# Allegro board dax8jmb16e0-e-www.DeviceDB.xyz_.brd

Outline 242.5 x 137.69 mm; copper layers: TOP, SVCC, IN1, IN2, SGND, BOTTOM. Coordinates in mm from the lower left corner of the outline.

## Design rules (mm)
net group W10(10)-T12B: nets HPOUT_L HPOUT_R
net group DFP-S4(4.5)W3.8(4.5)-T12B: nets C_TX0_HDMI+ C_TX0_HDMI- C_TX1_HDMI+ C_TX1_HDMI- C_TX2_HDMI+ C_TX2_HDMI- C_TXC_HDMI+ C_TXC_HDMI- CK_XDP_N CK_XDP_P CK_XDP_P_R CLK_PCIE_LANN CLK_PCIE_LANP CLK_PCIE_SSDN CLK_PCIE_SSDP CLK_PCIE_WLANN CLK_PCIE_WLANP CLK_PCIE_WWANN CLK_PCIE_WWANP DDI2_AUX_DN DDI2_AUX_DN_C DDI2_AUX_DP DDI2_AUX_DP_C DDI2_TX0_DN DDI2_TX0_DN_C DDI2_TX0_DP DDI2_TX0_DP_C DDI2_TX1_DN DDI2_TX1_DN_C DDI2_TX1_DP DDI2_TX1_DP_C DDI2_TX2_DN DDI2_TX2_DN_C DDI2_TX2_DP DDI2_TX2_DP_C DDI2_TX3_DN DDI2_TX3_DN_C DDI2_TX3_DP DDI2_TX3_DP_C EDIDCLK_R EDIDDATA_R IN_CLK IN_CLK# IN_D0 IN_D0# IN_D1 IN_D1# IN_D2 IN_D2# INT_EDP_AUXN INT_EDP_AUXP INT_EDP_TXN0 INT_EDP_TXN1 INT_EDP_TXP0 INT_EDP_TXP1 M_A_CLKN0 M_A_CLKN1 M_A_CLKP0 M_A_CLKP1 M_A_DQSN0 M_A_DQSN1 M_A_DQSN2 M_A_DQSN3 M_A_DQSN4 M_A_DQSN5 M_A_DQSN6 M_A_DQSN7 M_A_DQSP0 M_A_DQSP1 M_A_DQSP2 M_A_DQSP3 M_A_DQSP4 M_A_DQSP5 M_A_DQSP6 M_A_DQSP7 M_B_CLKN0 M_B_CLKN1 M_B_CLKP0 M_B_CLKP1 M_B_DQSN0 M_B_DQSN1 M_B_DQSN2 M_B_DQSN3 M_B_DQSN4 M_B_DQSN5 M_B_DQSN6 M_B_DQSN7 M_B_DQSP0 M_B_DQSP1 M_B_DQSP2 M_B_DQSP3 M_B_DQSP4 M_B_DQSP5 M_B_DQSP6 M_B_DQSP7 MDI0+ MDI0+_1 MDI0- MDI0-_1 MDI1+ MDI1+_1 MDI1- MDI1-_1 MDI2+ MDI2+_1 MDI2- MDI2-_1 MDI3+ MDI3+_1 MDI3- MDI3-_1 MUX_SBU1 MUX_SBU2 PCIE_RXN5_LAN PCIE_RXN5_LAN_L PCIE_RXN6_WLAN PCIE_RXN8_SSD PCIE_RXN9_SSD PCIE_RXN10_SSD PCIE_RXN10_WWAN PCIE_RXN11_SSD PCIE_RXN11_SSD_C PCIE_RXN12_SSD PCIE_RXN12_SSD_C PCIE_RXP5_LAN PCIE_RXP5_LAN_L PCIE_RXP6_WLAN PCIE_RXP8_SSD PCIE_RXP9_SSD PCIE_RXP10_SSD PCIE_RXP10_WWAN PCIE_RXP11_SSD PCIE_RXP11_SSD_C PCIE_RXP12_SSD PCIE_RXP12_SSD_C PCIE_TXN5_LAN PCIE_TXN5_LAN_C PCIE_TXN6_WLAN PCIE_TXN6_WLAN_C PCIE_TXN8_SSD PCIE_TXN9_SSD PCIE_TXN9_SSD_C PCIE_TXN10_SSD PCIE_TXN10_SSD_C1 PCIE_TXN10_WWAN PCIE_TXN10_WWAN_C PCIE_TXN11_SSD PCIE_TXN11_SSD_C PCIE_TXN12_SSD PCIE_TXN12_SSD_C PCIE_TXP5_LAN PCIE_TXP5_LAN_C PCIE_TXP6_WLAN PCIE_TXP6_WLAN_C PCIE_TXP8_SSD PCIE_TXP9_SSD PCIE_TXP9_SSD_C PCIE_TXP10_SSD PCIE_TXP10_SSD_C1 PCIE_TXP10_WWAN PCIE_TXP10_WWAN_C PCIE_TXP11_SSD PCIE_TXP11_SSD_C PCIE_TXP12_SSD PCIE_TXP12_SSD_C SATA_RXN7 SATA_RXN7_C SATA_RXP7 SATA_RXP7_C SATA_TXN7 SATA_TXN7_C SATA_TXP7 SATA_TXP7_C TX0_HDMI+ TX0_HDMI- TX1_HDMI+ TX1_HDMI- TX2_HDMI+ TX2_HDMI- TXC_HDMI+ TXC_HDMI- TXLOUT0+ TXLOUT0- TXLOUT1+ TXLOUT1- TYPEC_SBU1 TYPEC_SBU2 USB30_RX1+ USB30_RX1- USB30_RX3+ USB30_RX3- USB30_RX4+ USB30_RX4+_C USB30_RX4- USB30_RX4-_C USB30_TX1+ USB30_TX1+_C USB30_TX1- USB30_TX1-_C USB30_TX3+ USB30_TX3+_C USB30_TX3- USB30_TX3-_C USB30_TX4+ USB30_TX4+_C USB30_TX4- USB30_TX4-_C USB_CYPRESS_BOT_DN USB_CYPRESS_BOT_DP USB_CYPRESS_BOT_L_DN USB_CYPRESS_BOT_L_DP USB_CYPRESS_TOP_DN USB_CYPRESS_TOP_DP USB_CYPRESS_TOP_L_DN USB_CYPRESS_TOP_L_DP USBP1+ USBP1+_C USBP1- USBP1-_C USBP2+ USBP2- USBP3+_TS USBP3+_TS_C USBP3-_TS USBP3-_TS_C USBP4+_C USBP4-_C USBP5+ USBP5+_C USBP5- USBP5-_C USBP6+_C USBP6-_C USBP7+ USBP7- USBP10+_WWAN USBP10+_WWAN_C USBP10-_WWAN USBP10-_WWAN_C WR_CLK_DN WR_CLK_DP WR_LANE0_DN WR_LANE0_DP WR_LANE1_DN WR_LANE1_DP WT_CLK_DN WT_CLK_DP WT_LANE0_DN WT_LANE0_DP WT_LANE1_DN WT_LANE1_DP
net group DFP-S4.5(6)W3.8(4.5)-T12B: nets CK_XDP_N_R
net group DFP-S4.5(6)W4(5)-T12B: nets DPB_DDCCLK DPB_DDCDATA HDMI_UP_CLK HDMI_UP_DATA
net group DFP-S12(8)W3.8(4.5)-T12B: nets TYPEC3_RX1N TYPEC3_RX1N_C TYPEC3_RX1P TYPEC3_RX1P_C TYPEC3_RX2N TYPEC3_RX2N_C TYPEC3_RX2P TYPEC3_RX2P_C TYPEC3_TX1N TYPEC3_TX1N_C TYPEC3_TX1P TYPEC3_TX1P_C TYPEC3_TX2N TYPEC3_TX2N_C TYPEC3_TX2P TYPEC3_TX2P_C
net group W4(5)-T1B: nets H_CPU_SVIDALRT# PM_THRMTRIP# RTC_X1 RTC_X2 XTAL1 XTAL2 XTAL24_IN XTAL24_OUT
net group W4(5)-T12B: nets ACZ_BCLK ACZ_RST# ACZ_RST#_AUDIO ACZ_SDIN0 ACZ_SDOUT ACZ_SDOUT_AUDIO ACZ_SYNC ACZ_SYNC_AUDIO BIT_CLK_AUDIO CCG5_I2C_SCL_MUX CCG5_I2C_SDA_MUX CLK_PCI_EC_R CPU_PROCHOT# CPU_PROCHOT#_R DDR3_DRAMRST# DIGITAL_CLK DIGITAL_CLK_L DIGITAL_D1 EC_PECI EC_PECI_R FAN1_PWM H_VCCST_PWRGD HD_SDIN0 IM_5S_CLK IM_5S_DAT LAD0 LAD0_L LAD1 LAD1_L LAD2 LAD2_L LAD3 LAD3_L LFRAME# LPC_ESPI_CLK M_A_DQ0 M_A_DQ1 M_A_DQ2 M_A_DQ3 M_A_DQ4 M_A_DQ5 M_A_DQ6 M_A_DQ7 M_A_DQ8 M_A_DQ9 M_A_DQ10 M_A_DQ11 M_A_DQ12 M_A_DQ13 M_A_DQ14 M_A_DQ15 M_A_DQ16 M_A_DQ17 M_A_DQ18 M_A_DQ19 M_A_DQ20 M_A_DQ21 M_A_DQ22 M_A_DQ23 M_A_DQ24 M_A_DQ25 M_A_DQ26 M_A_DQ27 M_A_DQ28 M_A_DQ29 M_A_DQ30 M_A_DQ31 M_A_DQ32 M_A_DQ33 M_A_DQ34 M_A_DQ35 M_A_DQ36 M_A_DQ37 M_A_DQ38 M_A_DQ39 M_A_DQ40 M_A_DQ41 M_A_DQ42 M_A_DQ43 M_A_DQ44 M_A_DQ45 M_A_DQ46 M_A_DQ47 M_A_DQ48 M_A_DQ49 M_A_DQ50 M_A_DQ51 M_A_DQ52 M_A_DQ53 M_A_DQ54 M_A_DQ55 M_A_DQ56 M_A_DQ57 M_A_DQ58 M_A_DQ59 M_A_DQ60 M_A_DQ61 M_A_DQ62 M_A_DQ63 M_B_DQ0 M_B_DQ1 M_B_DQ2 M_B_DQ3 M_B_DQ4 M_B_DQ5 M_B_DQ6 M_B_DQ7 M_B_DQ8 M_B_DQ9 M_B_DQ10 M_B_DQ11 M_B_DQ12 M_B_DQ13 M_B_DQ14 M_B_DQ15 M_B_DQ16 M_B_DQ17 M_B_DQ18 M_B_DQ19 M_B_DQ20 M_B_DQ21 M_B_DQ22 M_B_DQ23 M_B_DQ24 M_B_DQ25 M_B_DQ26 M_B_DQ27 M_B_DQ28 M_B_DQ29 M_B_DQ30 M_B_DQ31 M_B_DQ32 M_B_DQ33 M_B_DQ34 M_B_DQ35 M_B_DQ36 M_B_DQ37 M_B_DQ38 M_B_DQ39 M_B_DQ40 M_B_DQ41 M_B_DQ42 M_B_DQ43 M_B_DQ44 M_B_DQ45 M_B_DQ46 M_B_DQ47 M_B_DQ48 M_B_DQ49 M_B_DQ50 M_B_DQ51 M_B_DQ52 M_B_DQ53 M_B_DQ54 M_B_DQ55 M_B_DQ56 M_B_DQ57 M_B_DQ58 M_B_DQ59 M_B_DQ60 M_B_DQ61 M_B_DQ62 M_B_DQ63 MUX_I2C_SCL MUX_I2C_SDA OUT_DPST_PWM PCH_DPST_PWM PCH_KBC_CLK PCH_KBC_DATA PCH_SMB_CLK PCH_SMB_DATA PCH_SMBCLK PCH_SMBDATA PCH_SPI1_CLK PCH_SPI1_CLK_E1 PCH_SPI1_CLK_E2 PCH_SPI1_CLK_R1 PCH_SPI1_CLK_R2 PCH_SPI1_SI PCH_SPI1_SI_E1 PCH_SPI1_SI_E2 PCH_SPI1_SI_R1 PCH_SPI1_SI_R2 PCH_SPI1_SO PCH_SPI1_SO_E1 PCH_SPI1_SO_E2 PCH_SPI1_SO_R1 PCH_SPI1_SO_R2 PCH_SPI_CS0# PCH_SPI_CS0#_R2 PCH_SPI_IO2 PCH_SPI_IO2_R1 PCH_SPI_IO2_R2 PCH_SPI_IO3 PCH_SPI_IO3_R1 PCH_SPI_IO3_R2 PCIE_CLKREQ5# PCIE_CLKREQ_LAN# PCIE_CLKREQ_SSD# PCIE_CLKREQ_WLAN# PD_I2C_SCL3 PD_I2C_SDA3 PLTRST# RSMRST# RTC_RST# S_SD_CLK S_SD_CLK_C S_SD_CMD S_SD_DATA0 S_SD_DATA1 S_SD_DATA2 S_SD_DATA3 SCL_BAT_CHG SD_CD#_BH SD_CD#_PCH SD_CLK SD_CLK_R SD_CMD SD_CMD_C SD_DATA0 SD_DATA0_C SD_DATA1 SD_DATA1_C SD_DATA2 SD_DATA2_C SD_DATA3 SD_DATA3_C SD_WP_BH SD_WP_PCH SDA_BAT_CHG SMB_ME0_CLK SMB_ME0_DAT SMB_PCH_CLK SMB_PCH_DAT SP_CLK SP_DATA SRTC_RST# SUSCLK32_KBC THERM_SCL THERM_SDA TPCLK-1 TPDATA-1 UIM_CLK UIM_DATA VADJ1 VCCSA_VCCSENSE VCCSA_VSSSENSE VCCSENSE VGT_VCCSENSE VGT_VSSSENSE VR_SVID_ALERT# VR_SVID_CLK VR_SVID_DATA VSSSENSE XCLK_BIASREF
net group W5(6.5)-T12B: nets M_A_A0 M_A_A1 M_A_A2 M_A_A3 M_A_A4 M_A_A5 M_A_A6 M_A_A7 M_A_A8 M_A_A9 M_A_A10 M_A_A11 M_A_A12 M_A_A13 M_A_ACT# M_A_ALERT# M_A_BG#0 M_A_BG#1 M_A_BS#0 M_A_BS#1 M_A_CAS# M_A_CKE0 M_A_CKE1 M_A_CS#0 M_A_CS#1 M_A_ODT0 M_A_ODT1 M_A_PARITY M_A_RAS# M_A_WE# M_B_A0 M_B_A1 M_B_A2 M_B_A3 M_B_A4 M_B_A5 M_B_A6 M_B_A7 M_B_A8 M_B_A9 M_B_A10 M_B_A11 M_B_A12 M_B_A13 M_B_ACT# M_B_ALERT# M_B_BG#0 M_B_BG#1 M_B_BS#0 M_B_BS#1 M_B_CAS# M_B_CKE0 M_B_CKE1 M_B_CS#0 M_B_CS#1 M_B_ODT0 M_B_ODT1 M_B_PARITY M_B_RAS# M_B_WE#
net group W5-T12B: nets TYPEC_VBUS
net group W8-T12B: nets DDR_VTT
net group W10-T12B: nets +1.0V_STG +SMDDR_VREF_DQ0 +SMDDR_VREF_DQ1 +VCCSFR +VCCST +VCCSTG CSP_C DDR_VTTREF
net group W12-T12B: nets PCIE_RCOMPN PCIE_RCOMPP SM_RCOMP_0 SM_RCOMP_1 SM_RCOMP_2
net group W15-T12B: nets CFG_RCOMP TYPEC_CC1 TYPEC_CC2
net group W20-T1B: nets EDP_RCOMP
net group W20-T12B: nets +3V_RTC +3V_WLAN_P +3VLCD_CON +5V_HDMIC +SMDDR_VREF_DIMM SM_VREF SMDDR_VREF_DQ0_M3 SMDDR_VREF_DQ1_M1 SMDDR_VREF_DQ1_M3
net group W30-T12B: nets L_SPK+ L_SPK+_R L_SPK- L_SPK-_R R_SPK+ R_SPK+_R R_SPK- R_SPK-_R
net group W40-T12B: nets +1.2V_VCCPLL_OC

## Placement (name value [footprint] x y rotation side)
C400  47P/50V_4  [C0402]  98.71 109.68 270 bottom
C401  *15P/50V_4  [C0402]  149.41 72.27 270 bottom
C402  *15P/50V_4  [C0402]  129.4 71.4 90 top
C403  0.1U/10V/X7R_4  [C0402]  128.84 59.42 180 top
C404  0.1U/16V_4  [C0402]  139.12 69.37 90 top
C405  0.1U/16V_4  [C0402]  152.85 99.39 0 top
C407  0.1U/16V_4  [C0402]  198.66 77.53 270 top
C409  0.1U/16V_4  [C0402]  199.63 77.53 270 top
C416  0.1U/16V_4  [C0402]  193.02 75.37 90 top
C417  0.1U/16V_4  [C0402]  194.04 75.37 90 top
C418  0.1U/16V_4  [C0402]  168.46 92.77 90 bottom
C419  0.1U/16V_4  [C0402]  167.5 92.77 90 bottom
C420  22P/50V_4  [C0402]  128.84 72.24 270 bottom
C421  15P/50V_4  [C0402]  155.61 83.37 0 top
C422  15P/50V_4  [C0402]  153.58 83.37 180 top
C423  *4.7p/50V_4  [C0402]  152.13 98.86 180 bottom
C424  10P/50V_4  [C0402]  145.67 101.65 180 bottom
C425  10P/50V_4  [C0402]  145.68 100.16 180 bottom
C426  1U/6.3V_4  [C0402]  134.07 72.22 90 bottom
C427  0.1U/16V_4  [C0402]  133.1 72.22 90 bottom
C428  1U/6.3V_4  [C0402]  61.5 59.92 0 top
C429  *1U/6.3V_4  [C0402]  61.5 60.89 0 top
C430  1U/6.3V_4  [C0402]  131.66 71.86 180 bottom
C431  0.1U/16V_4  [C0402]  132.93 89.01 90 top
C432  1U/6.3V_4  [C0402]  133.05 92.89 90 top
C433  1U/6.3V_4  [C0402]  131.94 89.01 90 top
C434  *1U/6.3V_4  [C0402]  130.81 91.45 180 top
C435  *0.1U/16V_4  [C0402]  130.95 89.03 90 top
C436  0.1U/16V_4  [C0402]  151.52 103.69 270 bottom
C437  1U/6.3V_4  [C0402]  152 105.09 180 bottom
C438  1U/6.3V_4  [C0402]  132 87 270 top
C439  0.1U/16V_4  [C0402]  125.99 89.11 90 top
C440  0.1U/16V_4  [C0402]  131.73 92.89 90 top
C441  1U/6.3V_4  [C0402]  152.54 103.69 90 bottom
C442  0.1U/16V_4  [C0402]  130.81 90.45 180 top
C443  *1U/6.3V_4  [C0402]  152 107.12 180 bottom
C444  1U/6.3V_4  [C0402]  152 106.1 180 bottom
C445  *0.1U/16V_4  [C0402]  154.54 103.69 270 bottom
C446  0.1U/16V_4  [C0402]  129.2 92.74 90 top
C447  0.1U/16V_4  [C0402]  131.04 87 270 top
C448  1U/6.3V_4  [C0402]  129.83 86.97 270 top
C449  0.1U/16V_4  [C0402]  142.38 86.87 0 bottom
C450  1U/6.3V_4  [C0402]  127.97 89.01 90 top
C451  10U/6.3V_4  [C0402]  156.45 104.32 180 bottom
C452  0.1U/16V_4  [C0402]  129.82 94.55 90 top
C453  *0.1U/16V_4  [C0402]  129.17 90.76 270 top
C454  1U/6.3V_4  [C0402]  153.53 103.69 270 bottom
C455  0.1U/16V_4  [C0402]  131.17 95.04 90 top
C456  1U/6.3V_4  [C0402]  127.92 92.8 90 top
C457  0.1U/16V_4  [C0402]  132.42 90.78 270 top
C458  1U/6.3V_4  [C0402]  127.16 86.54 180 top
C459  1U/6.3V_4  [C0402]  132.42 94.9 90 top
C460  0.1U/16V_4  [C0402]  128.47 94.54 90 top
C461  1U/6.3V_4  [C0402]  127.23 94.54 90 top
C462  0.1U/16V_4  [C0402]  152.74 92.49 270 top
C463  1U/6.3V_4  [C0402]  129.93 89.01 90 top
C464  1U/6.3V_4  [C0402]  130.49 92.82 90 top
C465  1U/6.3V_4  [C0402]  128.94 89.01 90 top
C466  1U/6.3V_4  [C0402]  127.92 91.06 270 top
C467  *0.1U/16V_4  [C0402]  142.37 84.88 0 bottom
C468  0.1U/16V_4  [C0402]  148.83 117.12 180 bottom
C469  1U/6.3V_4  [C0402]  148.83 116.13 180 bottom
C470  1U/6.3V_4  [C0402]  126.96 89.11 90 top
C471  0.1U/16V_4  [C0402]  130.01 72.27 90 bottom
C472  1U/6.3V_4  [C0402]  142.32 99.32 0 bottom
C473  22U/6.3V_6  [C0603]  145.15 97.93 180 bottom
C474  1U/6.3V_4  [C0402]  128.64 108.55 180 bottom
C475  *0.1U/16V_4  [C0402]  128.18 109.35 180 top
C476  22U/6.3V_6  [C0603]  128.77 110.06 180 bottom
C477  *3P/50V_4  [C0402]  128.18 108.39 180 top
C478  *3P/50V_4  [C0402]  128.18 106.05 0 top
C481  10U/6.3V_4  [C0402]  116.87 96.88 180 top
C482  10U/6.3V_4  [C0402]  120.51 91.52 0 top
C483  10U/6.3V_4  [C0402]  115.12 88.12 180 top
C485  10U/6.3V_4  [C0402]  114.16 96.91 180 top
C486  10U/6.3V_4  [C0402]  120.51 93.05 180 top
C490  10U/6.3V_4  [C0402]  120.61 96.88 0 top
C491  10U/6.3V_4  [C0402]  111.03 94.57 90 top
C492  10U/6.3V_4  [C0402]  112.99 94.57 90 top
C493  10U/6.3V_4  [C0402]  120.81 86.04 0 top
C494  10U/6.3V_4  [C0402]  120.48 88.4 180 top
C495  10U/6.3V_4  [C0402]  120.79 94.39 180 top
C496  10U/6.3V_4  [C0402]  120.51 90 180 top
C497  10U/6.3V_4  [C0402]  120.79 95.36 180 top
C508  10U/6.3V_4  [C0402]  113.75 85.91 180 top
C509  10U/6.3V_4  [C0402]  115.48 85.96 0 top
C510  10U/6.3V_4  [C0402]  119.06 86.04 0 top
C518  10U/6.3V_4  [C0402]  115.5 86.92 0 top
C519  10U/6.3V_4  [C0402]  117.33 87.03 180 top
C520  10U/6.3V_4  [C0402]  117.84 93.4 180 top
C521  10U/6.3V_4  [C0402]  120.81 87 0 top
C522  10U/6.3V_4  [C0402]  117.33 86.06 180 top
C523  10U/6.3V_4  [C0402]  117.86 88.6 180 top
C524  10U/6.3V_4  [C0402]  117.97 95.92 180 top
C525  22U/6.3V_6  [C0603]  117.84 89.97 0 top
C526  22U/6.3V_6  [C0603]  123.5 112.93 270 top
C527  22U/6.3V_6  [C0603]  112.89 113.72 270 top
C528  22U/6.3V_6  [C0603]  114.79 95.69 180 top
C529  22U/6.3V_6  [C0603]  119.39 112.91 270 top
C530  22U/6.3V_6  [C0603]  115.17 89.97 180 top
C531  22U/6.3V_6  [C0603]  114.79 94.16 180 top
C532  22U/6.3V_6  [C0603]  113.52 106.1 0 top
C533  22U/6.3V_6  [C0603]  121.42 112.91 270 top
C534  22U/6.3V_6  [C0603]  114.79 92.13 180 top
C535  22U/6.3V_6  [C0603]  109.23 112.91 270 top
C536  22U/6.3V_6  [C0603]  117.46 92.13 0 top
C537  22U/6.3V_6  [C0603]  117.97 94.67 0 top
C538  10U/6.3V_4  [C0402]  112 94.57 90 top
C539  10U/6.3V_4  [C0402]  112.89 107.5 180 top
C540  10U/6.3V_4  [C0402]  118.58 109.28 0 bottom
C541  10U/6.3V_4  [C0402]  116.57 109.28 180 bottom
C546  *0.1U/16V_4  [C0402]  105.72 111.13 0 bottom
C547  22U/6.3V_6  [C0603]  107.22 87.05 90 top
C548  22U/6.3V_6  [C0603]  102.85 87.05 90 top
C549  22U/6.3V_6  [C0603]  101.41 87.05 270 top
C550  22U/6.3V_6  [C0603]  101.84 92.26 0 top
C551  22U/6.3V_6  [C0603]  83.52 90 90 bottom
C552  22U/6.3V_6  [C0603]  104.88 92.26 0 top
C553  22U/6.3V_6  [C0603]  105.77 87.05 90 top
C554  22U/6.3V_6  [C0603]  104.88 94.42 180 top
C555  22U/6.3V_6  [C0603]  108.64 87.05 90 top
C556  22U/6.3V_6  [C0603]  85.05 90 90 bottom
C557  22U/6.3V_6  [C0603]  99.93 87.05 270 top
C558  22U/6.3V_6  [C0603]  87.51 90.02 90 bottom
C559  10U/6.3V_4  [C0402]  104.88 90.53 180 top
C560  10U/6.3V_4  [C0402]  86.14 94.93 90 top
C561  10U/6.3V_4  [C0402]  101.84 90.61 180 top
C562  10U/6.3V_4  [C0402]  87.13 94.93 90 top
C563  22U/6.3V_6  [C0603]  89.04 90.02 90 bottom
C564  22U/6.3V_6  [C0603]  104.33 87.05 270 top
C565  10U/6.3V_4  [C0402]  89.11 92.74 90 top
C566  10U/6.3V_4  [C0402]  86.24 90.1 270 bottom
C567  10U/6.3V_4  [C0402]  88.12 86.42 270 top
C568  10U/6.3V_4  [C0402]  87.1 86.42 270 top
C569  10U/6.3V_4  [C0402]  107.3 90.3 0 top
C570  10U/6.3V_4  [C0402]  99.93 92.39 270 top
C571  10U/6.3V_4  [C0402]  89.14 86.42 270 top
C572  10U/6.3V_4  [C0402]  88.12 92.72 90 top
C573  10U/6.3V_4  [C0402]  89.06 94.93 270 top
C574  10U/6.3V_4  [C0402]  100.44 95.81 180 top
C575  10U/6.3V_4  [C0402]  102.2 95.73 0 top
C576  10U/6.3V_4  [C0402]  102.22 93.53 0 top
C577  10U/6.3V_4  [C0402]  88.1 94.93 270 top
C578  10U/6.3V_4  [C0402]  90.15 86.42 270 top
C579  10U/6.3V_4  [C0402]  90.03 94.93 270 top
C580  10U/6.3V_4  [C0402]  100.44 93.78 180 top
C581  10U/6.3V_4  [C0402]  90.13 92.72 90 top
C582  10U/6.3V_4  [C0402]  100.44 94.8 180 top
C583  10U/6.3V_4  [C0402]  99.96 90.66 270 top
C584  10U/6.3V_4  [C0402]  104.02 95.89 0 top
C585  10U/6.3V_4  [C0402]  102.22 94.67 0 top
C586  10U/6.3V_4  [C0402]  101.58 108.77 90 bottom
C587  10U/6.3V_4  [C0402]  108.59 95.94 180 top
C588  10U/6.3V_4  [C0402]  106.74 95.97 0 top
C589  10U/6.3V_4  [C0402]  110.45 95.97 180 top
C590  10U/6.3V_4  [C0402]  109.36 88.98 180 top
C591  10U/6.3V_4  [C0402]  111.11 88.19 180 top
C592  10U/6.3V_4  [C0402]  102.98 106.25 270 bottom
C593  10U/6.3V_4  [C0402]  112.17 95.92 0 top
C594  10U/6.3V_4  [C0402]  109.1 90.3 180 top
C595  10U/6.3V_4  [C0402]  111.77 92.77 0 top
C596  10U/6.3V_4  [C0402]  111.77 91.72 0 top
C597  *10U/6.3V_4  [C0402]  114.64 71.63 90 top
C598  1U/6.3V_4  [C0402]  111.74 110.19 0 bottom
C599  1U/6.3V_4  [C0402]  111.74 109.15 0 bottom
C600  1U/6.3V_4  [C0402]  126.55 92.84 0 top
C601  1U/6.3V_4  [C0402]  122.54 86.06 180 top
C602  *10U/6.3V_4  [C0402]  116.95 75.49 270 top
C603  *1U/6.3V_4  [C0402]  102.32 75.39 90 top
C604  1U/6.3V_4  [C0402]  111.41 73.56 270 top
C605  1U/6.3V_4  [C0402]  111.41 71.79 270 top
C606  1U/6.3V_4  [C0402]  121.19 75.14 270 top
C607  10U/6.3V_4  [C0402]  111.23 86.97 180 top
C608  10U/6.3V_4  [C0402]  112.89 88.19 0 top
C609  1U/6.3V_4  [C0402]  126.53 91.42 0 top
C610  1U/6.3V_4  [C0402]  122.54 87.03 180 top
C611  1U/6.3V_4  [C0402]  122.54 88.24 180 top
C612  1U/6.3V_4  [C0402]  111.23 86.01 180 top
C613  10U/6.3V_4  [C0402]  102.32 73.61 90 top
C614  10U/6.3V_4  [C0402]  111.41 75.34 270 top
C615  10U/6.3V_4  [C0402]  117.05 72.7 270 top
C616  10U/6.3V_4  [C0402]  121.24 72.5 90 top
C617  1U/6.3V_4  [C0402]  125.81 86.47 270 top
C618  1U/6.3V_4  [C0402]  122.54 91.24 180 top
C619  1U/6.3V_4  [C0402]  123.88 86.44 270 top
C620  1U/6.3V_4  [C0402]  124.57 92.26 0 top
C621  1U/6.3V_4  [C0402]  124.57 95.31 0 top
C622  1U/6.3V_4  [C0402]  122.54 94.29 180 top
C623  1U/6.3V_4  [C0402]  122.54 95.31 180 top
C624  10U/6.3V_4  [C0402]  124.57 90.23 0 top
C625  10U/6.3V_4  [C0402]  122.54 92.26 180 top
C626  10U/6.3V_4  [C0402]  124.57 89.21 0 top
C627  10U/6.3V_4  [C0402]  124.57 88.19 0 top
C628  10U/6.3V_4  [C0402]  124.57 94.29 0 top
C629  10U/6.3V_4  [C0402]  124.57 93.27 0 top
C630  10U/6.3V_4  [C0402]  124.57 96.58 0 top
C631  1U/6.3V_4  [C0402]  124.85 86.47 270 top
C632  10U/6.3V_4  [C0402]  122.54 96.32 180 top
C633  *10U/6.3V_4  [C0402]  122.54 89.21 180 top
C634  10U/6.3V_4  [C0402]  122.54 93.27 180 top
C635  *10U/6.3V_4  [C0402]  122.54 90.23 180 top
C636  10U/6.3V_4  [C0402]  124.57 91.24 0 top
C637  10U/6.3V_4  [C0402]  121.7 123.47 0 bottom
C638  47U/6.3V_8  [C0805]  129.08 96.4 180 top
C639  1U/6.3V_4  [C0402]  120.79 105.39 180 bottom
C640  1U/6.3V_4  [C0402]  126.05 95.89 270 top
C641  *3.3P/50V_4  [C0402]  104.02 111.74 90 bottom
C2800  *0.1U/10V_4  [C0402]  73.52 39.86 180 top
C2801  1U/6.3V_4  [C0402]  75.4 42.75 270 top
C2802  1U/6.3V_4  [C0402]  83.45 41.92 180 top
C2803  1U/6.3V_4  [C0402]  76.16 39.88 180 top
C2804  1U/6.3V_4  [C0402]  61.25 40.7 0 top
C2805  1U/6.3V_4  [C0402]  55.2 40.65 180 top
C2806  1U/6.3V_4  [C0402]  63 40.7 180 top
C2807  1U/6.3V_4  [C0402]  99.5 40.06 0 top
C2808  1U/6.3V_4  [C0402]  87.87 39.58 270 top
C2809  10U/6.3V_4  [C0402]  52.12 41.05 90 top
C2810  10U/6.3V_4  [C0402]  85.91 39.58 270 top
C2811  10U/6.3V_4  [C0402]  104.78 42.4 90 top
C2812  10U/6.3V_4  [C0402]  110.83 42.98 270 top
C2813  10U/6.3V_4  [C0402]  71.51 41.18 0 top
C2814  10U/6.3V_4  [C0402]  98.08 43.41 180 top
C2815  10U/6.3V_4  [C0402]  94.65 42.32 0 top
C2816  10U/6.3V_4  [C0402]  57.39 41.1 180 top
C2817  1U/6.3V_4  [C0402]  113.39 37.32 90 top
C2818  1U/6.3V_4  [C0402]  112.38 37.32 90 top
C2819  1U/6.3V_4  [C0402]  116.77 39.2 270 top
C2820  1U/6.3V_4  [C0402]  115.73 39.45 270 top
C2821  10U/6.3V_4  [C0402]  117.43 37.32 90 top
C2822  *0.1U/16V_4  [C0402]  119.34 38.46 0 top
C2823  *2.2U/10V_4  [C0402]  119.34 39.48 0 top
C2824  0.1U/16V_4  [C0402]  116.95 43.11 90 top
C2825  2.2U/10V_4  [C0402]  115.98 43.19 90 top
C2826  0.1U/16V_4  [C0402]  111.44 41.08 0 top
C2827  2.2U/10V_4  [C0402]  113.52 41.64 180 top
C2828  0.022U/25V_4  [C0402]  119.26 43.21 0 top
C2829  *0.1U/10V_4  [C0402]  151.34 40.59 180 top
C2830  1U/6.3V_4  [C0402]  171.99 39.6 90 top
C2831  1U/6.3V_4  [C0402]  185.5 37.93 270 top
C2832  1U/6.3V_4  [C0402]  142.76 40.59 0 top
C2833  1U/6.3V_4  [C0402]  186.5 37.93 270 top
C2834  1U/6.3V_4  [C0402]  166.48 39.63 270 top
C2835  1U/6.3V_4  [C0402]  187.51 37.93 270 top
C2836  1U/6.3V_4  [C0402]  176.16 41.92 0 top
C2837  1U/6.3V_4  [C0402]  190.31 37.9 270 top
C2838  1U/6.3V_4  [C0402]  144.48 42.63 270 top
C2839  10U/6.3V_4  [C0402]  182.79 38.16 270 top
C2840  1U/6.3V_4  [C0402]  163.18 42.68 90 top
C2841  1U/6.3V_4  [C0402]  164.6 42.58 90 top
C2842  0.1U/16V_4  [C0402]  190.61 44.48 0 top
C2843  1U/6.3V_4  [C0402]  138.82 40.57 0 top
C2844  2.2U/10V_6  [C0603]  189.7 45.67 0 top
C2845  10U/6.3V_4  [C0402]  136.46 43.26 270 top
C2846  10U/6.3V_4  [C0402]  128.43 40.67 0 top
C2847  10U/6.3V_4  [C0402]  161.98 43.11 90 top
C2848  10U/6.3V_4  [C0402]  163.3 39.65 270 top
C2849  *0.1U/16V_4  [C0402]  193.33 43.08 180 top
C2850  10U/6.3V_4  [C0402]  155.3 42.86 0 top
C2851  *2.2U/10V_6  [C0603]  193.28 44.28 180 top
C2852  10U/6.3V_4  [C0402]  178.53 40.98 90 top
C2853  10U/6.3V_4  [C0402]  162.59 37.47 180 top
C2854  10U/6.3V_4  [C0402]  168.64 40.98 0 top
C2855  *0.1U/16V_4  [C0402]  123.3 38.99 180 top
C2856  *2.2U/10V_6  [C0603]  123.3 37.67 180 top
C2857  0.022U/25V_4  [C0402]  121.95 43.24 180 top
C3300  0.1U/16V_4  [C0402]  15.1 101.28 0 top
C3301  0.022U/25V_4  [C0402]  126.63 122.13 0 top
C3401  0.1U/25V_4  [C0402]  45.35 125.66 180 top
C3402  33P/50V_4  [C0402]  40.9 130.38 90 top
C3403  0.01U/50V_4  [C0402]  45.65 126.65 0 top
C3404  0.1U/16V_4  [C0402]  22.97 130.76 0 top
C3405  82P/50V_4  [C0402]  31.02 129.19 0 top
C3406  0.01U/50V_4  [C0402]  31.35 127.06 0 top
C3407  0.1U/16V_4  [C0402]  31.35 128.07 0 top
C3408  10U/6.3V_4  [C0402]  30.92 126.07 0 top
C3409  2200P/50V_4  [C0402]  31.02 130.15 180 top
C3410  0.047U/25V_4  [C0402]  32.75 132.14 0 top
C3411  10P/50V_4  [C0402]  39.94 130.38 90 top
C3412  10P/50V_4  [C0402]  38.95 130.38 90 top
C3413  1000P/50V_4  [C0402]  44.66 130.51 270 top
C3414  0.1U/16V_4  [C0402]  35.92 130.13 90 top
C3415  0.1U/16V_4  [C0402]  34.91 130.13 90 top
C3416  0.1U/16V_4  [C0402]  37.96 130.21 90 top
C3417  0.1U/16V_4  [C0402]  36.94 130.21 90 top
C3418  0.1U/16V_4  [C0402]  33.89 127.08 90 top
C3419  0.1U/16V_4  [C0402]  32.88 127.08 90 top
C3420  0.1U/16V_4  [C0402]  22.97 129.75 0 top
C3421  *0.01u/50V_4  [C0402]  42.53 132.14 0 top
C3422  *4.7u/6.3V_4  [C0402]  43.54 128.96 0 top
C3423  *22U/6.3V_6  [C0603]  22.84 127.06 90 top
C3424  *100p/50V_4  [C0402]  16.62 115.88 180 top
C3500  0.1U/16V_4  [C0402]  226.47 70.08 180 bottom
C3501  *0.01u/50V_4  [C0402]  227.03 65.97 0 bottom
C3502  0.1U/16V_4  [C0402]  227.03 66.96 0 bottom
C3503  *10U/6.3V_4  [C0402]  227.06 69.02 0 bottom
C3504  0.1U/16V_4  [C0402]  215.35 83.04 270 top
C3505  0.1U/16V_4  [C0402]  211.18 86.06 270 top
C3506  0.1U/16V_4  [C0402]  215.98 94.02 90 top
C3507  0.1U/16V_4  [C0402]  212 84.71 0 top
C3508  0.1U/16V_4  [C0402]  214.56 94.32 90 top
C3509  0.1U/16V_4  [C0402]  209.93 93.27 0 top
C3510  0.1U/16V_4  [C0402]  209.93 92.26 0 top
C3511  0.1U/16V_4  [C0402]  209.83 91.24 0 top
C3512  0.1U/16V_4  [C0402]  209.83 90.23 0 top
C3513  0.1U/16V_4  [C0402]  209.83 89.21 0 top
C3514  0.1U/16V_4  [C0402]  209.83 88.19 0 top
C3515  0.1U/16V_4  [C0402]  209.83 87.23 0 top
C3516  0.1U/16V_4  [C0402]  209.84 86.21 0 top
C3517  *10P/50V_4  [C0402]  226.66 63.73 90 bottom
C3518  *10P/50V_4  [C0402]  227.92 63.73 90 bottom
C3519  *0.01u/50V_4  [C0402]  227.03 67.95 0 bottom
C3520  *220P/50V_4  [C0402]  229.62 62.36 0 top
C3601  100P/50V_4  [C0402]  226.2 16.21 270 top
C3603  100P/50V_4  [C0402]  225.84 10.27 180 top
C3608  10U/6.3V_4  [C0402]  223.4 25.33 90 top
C3609  0.1U/16V_4  [C0402]  223.32 22.76 90 top
C3610  10U/6.3V_4  [C0402]  219.23 8.29 180 top
C3611  0.1U/16V_4  [C0402]  216.8 23.12 180 top
C3613  10P/50V_4  [C0402]  213.8 15.02 180 top
C3615  10U/6.3V_4  [C0402]  224.04 8.64 0 top
C3616  2.2U/10V_4  [C0402]  224.04 9.61 180 top
C3617  1u/25V_6  [C0603]  225 15.19 90 top
C3618  1u/25V_6  [C0603]  223.55 14.99 90 top
C3619  10U/6.3V_4  [C0402]  222.08 22.05 90 top
C3620  0.1U/16V_4  [C0402]  222.21 7.57 180 top
C3621  10U/6.3V_4  [C0402]  222.21 8.54 0 top
C3622  *22P/50V_4  [C0402]  213.09 12.1 180 top
C3623  10U/6.3V_4  [C0402]  213.11 11.13 180 top
C3624  10U/6.3V_4  [C0402]  212.99 7.85 270 top
C3625  0.1U/16V_4  [C0402]  203.13 9.3 0 top
C3626  10U/6.3V_4  [C0402]  213.8 16.08 180 top
C3627  0.1U/16V_4  [C0402]  203.13 10.29 0 top
C3628  10U/6.3V_4  [C0402]  223.51 17.17 270 top
C3629  10U/6.3V_4  [C0402]  222.16 17.55 180 top
C3630  10U/6.3V_4  [C0402]  219.72 21.6 0 top
C3631  0.1U/16V_4  [C0402]  217.74 17.38 180 top
C3632  10U/6.3V_4  [C0402]  219.72 22.59 0 top
C3633  0.1U/16V_4  [C0402]  220.07 20.63 180 top
C3634  0.1U/16V_4  [C0402]  216.83 8.54 180 top
C3635  1000P/50V_4  [C0402]  163.05 127.82 90 top
C3636  1000P/50V_4  [C0402]  163.18 125.48 270 top
C3637  1000P/50V_4  [C0402]  163.28 123.5 180 top
C3638  1000P/50V_4  [C0402]  164.42 119.99 180 top
C3639  *100p/50V_4  [C0402]  210.52 6.82 0 top
C3640  100P/50V_4  [C0402]  227.49 22.36 0 top
C4000  10P/50V_4  [C0402]  190.94 61.92 90 top
C4001  10P/50V_4  [C0402]  189.59 59.97 180 top
C4002  0.1U/16V_4  [C0402]  188.93 70.13 270 top
C4003  0.1U/16V_4  [C0402]  189.95 70.13 270 top
C4004  *0.1U/16V_4  [C0402]  190.22 64.47 0 top
C4005  0.1U/16V_4  [C0402]  196.58 67.62 0 bottom
C4006  4.7U/6.3VS_4  [C0402]  196.58 66.65 0 bottom
C4007  0.1U/16V_4  [C0402]  198.61 69.55 180 top
C4008  0.1U/16V_4  [C0402]  196.58 68.59 0 bottom
C4009  0.1U/16V_4  [C0402]  189.7 66.99 270 top
C4010  0.1U/16V_4  [C0402]  195.31 63.05 90 top
C4011  *1U/6.3V_4  [C0402]  188.35 67.52 0 top
C4012  0.1U/16V_4  [C0402]  190.71 66.99 270 top
C4013  1000P/50V_4  [C0402]  225.92 93.15 180 top
C4014  1000P/50V_4  [C0402]  228.07 97.85 90 top
C4015  22U/6.3V_6  [C0603]  199.54 63.89 90 top
C4016  4.7U/6.3VS_4  [C0402]  198.41 71.51 180 top
C4017  0.1U/16V_4  [C0402]  197.34 63.91 90 top
C4018  0.1U/16V_4  [C0402]  196.4 69.93 90 bottom
C4019  *4.7U/6.3VS_4  [C0402]  196.73 71.84 270 top
C4020  *4.7U/6.3VS_4  [C0402]  198.31 63.91 90 top
C4021  4.7U/6.3VS_4  [C0402]  187.8 64.95 90 top
C4022  0.1U/16V_4  [C0402]  188.79 64.95 90 top
C4023  0.01U/50V_4  [C0402]  209.89 71.56 270 top
C4024  10P/3KV_1808  [CC1808]  222.92 60.79 90 bottom
C4035  *0.1U/16V_4  [C0402]  195.74 71.84 270 top
C4036  *10P/50V_4  [C0402]  230.01 106.28 270 bottom
C4037  *10P/50V_4  [C0402]  228.13 82.17 180 bottom
C4100  0.1U/16V_4  [C0402]  176.49 93.17 270 top
C4101  0.1U/16V_4  [C0402]  177.96 92.79 270 bottom
C4102  4.7U/6.3V_4  [C0402]  178.98 92.79 90 bottom
C4104  4.7U/6.3V_4  [C0402]  162.29 93.27 270 bottom
C4105  0.1U/16V_4  [C0402]  160.82 93.15 270 bottom
C4106  *390P/50V_4  [C0402]  174.3 92.74 90 bottom
C4107  *0.1U/16V_4  [C0402]  182.33 88.12 180 top
C4108  *4.7p/50V_4  [C0402]  172.35 92.74 270 bottom
C4109  1u/6.3V_4  [C0402]  185.73 91.24 180 top
C4200  56P/50V_4  [C0402]  188.7 83.93 0 bottom
C4201  *6.8P/50V_4  [C0402]  191.14 79.79 90 top
C4202  *8.2P/50V_4  [C0402]  210.88 79.1 270 bottom
C4203  0.1U/16V_4_X7R  [C0402]  209.89 79.1 90 bottom
C4204  *18P/50V_4  [C0402]  204.61 86.06 90 bottom
C4205  4.7U/6.3V_4  [C0402]  206.28 80.12 90 top
C4207  10U/6.3V_4  [C0402]  188.7 82.89 180 bottom
C4208  *39P/50V_4  [C0402]  204.68 79.74 0 top
C4209  0.1U/16V_4  [C0402]  208.25 65.47 270 bottom
C4210  4.7U/6.3V_4  [C0402]  209.22 64.63 270 bottom
C4211  18P/50V_4  [C0402]  207.28 66.03 90 bottom
C4222  0.1U/16V_4  [C0402]  196.81 80.4 0 top
C4236  *18P/50V_4  [C0402]  201.91 82.2 90 bottom
C4237  *18P/50V_4  [C0402]  203.69 82.2 90 bottom
C4238  *0.1U/16V_4  [C0402]  195.16 76.31 90 top
C4300  *0.01u/50V_4  [C0402]  210.36 16.21 180 top
C4301  *0.01u/50V_4  [C0402]  210.36 17.48 180 top
C4302  0.1U/16V_4  [C0402]  204.38 24.49 90 bottom
C4303  1000P/50V_4  [C0402]  199.68 9.84 90 bottom
C4304  0.1U/16V_4  [C0402]  202.14 9.76 90 bottom
C4305  2200P/50V_4  [C0402]  200.67 9.84 90 bottom
C4306  *0.01u/50V_4  [C0402]  208.3 18.47 0 top
C4307  *0.01u/50V_4  [C0402]  208.25 19.59 0 top
C4308  0.22U/10V_4  [C0402]  210.36 14.08 0 top
C4309  0.22U/10V_4  [C0402]  210.36 15.09 0 top
C4310  0.22U/10V_4  [C0402]  210.35 18.47 180 top
C4311  0.22U/10V_4  [C0402]  210.35 19.59 180 top
C4312  3.3P/50V_4  [C0402]  202.34 24.49 90 bottom
C4313  68P/50V_4  [C0402]  203.39 24.49 90 bottom
C4314  0.22U/10V_4  [C0402]  210.51 7.78 0 top
C4315  0.22U/10V_4  [C0402]  210.51 8.8 0 top
C4316  0.22U/10V_4  [C0402]  210.36 9.94 0 top
C4317  0.22U/10V_4  [C0402]  210.36 10.95 0 top
C4318  *0.1U/16V_4  [C0402]  204.28 16.84 270 bottom
C4400  *22P/50V_4  [C0402]  221.87 24.86 270 bottom
C4401  *15P/50V_4  [C0402]  222.84 24.86 270 bottom
C4402  0.1U/16V_4  [C0402]  223.85 24.86 270 bottom
C4403  10U/6.3V_4  [C0402]  226.23 24.19 180 bottom
C4404  0.01U/50V_4  [C0402]  220.91 24.89 90 bottom
C4405  0.01U/50V_4  [C0402]  219.95 24.89 90 bottom
C4406  0.01U/50V_4  [C0402]  218.98 24.87 90 bottom
C4407  0.01U/50V_4  [C0402]  218.02 24.87 90 bottom
C4700  10U/6.3V_4  [C0402]  196.02 40.49 0 top
C4701  10U/6.3V_4  [C0402]  211.59 49.64 180 top
C4702  0.1U/16V_4  [C0402]  211.59 50.65 180 top
C4703  0.1U/16V_4  [C0402]  196.02 41.48 0 top
C4704  *10P/50V_4  [C0402]  215.48 50.86 0 top
C4705  *10U/6.3V_4  [C0402]  212.94 60.36 90 top
C4706  0.1U/16V_4  [C0402]  213.9 60.36 270 top
C4708  1uF/6.3V_4  [C0402]  197.67 51.92 180 top
C4710  2200P/50V_4  [C0402]  198.66 44.1 90 top
C4711  2200P/50V_4  [C0402]  191.88 49.28 180 top
C4712  4.7U/6.3V_4  [C0402]  198.08 48.62 270 top
C4713  0.1U/16V_4  [C0402]  211.46 53.78 0 top
C4714  0.1U/16V_4  [C0402]  196.2 57.87 270 top
C4715  0.1U/16V_4  [C0402]  197.47 53.24 180 top
C4716  0.1U/16V_4  [C0402]  197.93 57.82 270 top
C4717  0.1U/16V_4  [C0402]  217.26 45.99 180 bottom
C4718  10U/6.3V_4  [C0402]  197.32 43.67 180 top
C4719  0.1U/16V_4  [C0402]  197.32 44.63 0 top
C4720  *0.1U/16V_4  [C0402]  213.65 51.31 0 top
C4721  0.1U/16V_4  [C0402]  212.66 45.98 180 top
C4722  1U/6.3V_4  [C0402]  194.37 52.3 180 top
C4723  *390P/50V_4  [C0402]  211.49 52.74 0 top
C4724  *EGA10402V05AH_0.2p  [R0402]  231.1 84.1 0 top
C4725  *EGA10402V05AH_0.2p  [R0402]  231.1 83.11 0 top
C4726  2200P/50V_4  [C0402]  203.41 46.11 0 top
C4727  2200P/50V_4  [C0402]  203.83 44.51 180 top
C4728  0.1u/6.3V_2  [C0201]  210.96 51.69 90 top
C4729  *0.1U/16V_4  [C0402]  190.74 53.19 180 top
C5000  0.1U/16V_4  [C0402]  39.36 56.81 180 top
C5001  *1uF/6.3V_4  [C0402]  137.9 15.78 180 bottom
C5003  220p/25V_2  [C0201]  51.8 26.73 0 bottom
C5004  220p/25V_2  [C0201]  52.43 30.79 180 bottom
C5005  220p/25V_2  [C0201]  52.81 26.73 180 bottom
C5006  220p/25V_2  [C0201]  50.45 28.58 270 bottom
C5007  220p/25V_2  [C0201]  52.81 28.5 180 bottom
C5008  220p/25V_2  [C0201]  54.34 26.73 0 bottom
C5009  220p/25V_2  [C0201]  50.53 30.03 180 bottom
C5010  220p/25V_2  [C0201]  54.34 28.5 0 bottom
C5011  220p/25V_2  [C0201]  51.74 28.31 0 bottom
C5012  220p/25V_2  [C0201]  51.67 34.35 180 top
C5013  220p/25V_2  [C0201]  51.54 30.03 0 bottom
C5014  220p/25V_2  [C0201]  56.52 32.82 270 bottom
C5015  220p/25V_2  [C0201]  54.59 33.08 180 bottom
C5016  220p/25V_2  [C0201]  46.48 45.88 0 top
C5017  220p/25V_2  [C0201]  40.83 40.75 90 top
C5018  220p/25V_2  [C0201]  52.76 32.26 0 top
C5019  220p/25V_2  [C0201]  52.81 34.35 0 top
C5020  220p/25V_2  [C0201]  51.67 32.82 180 bottom
C5021  220p/25V_2  [C0201]  52.69 32.82 0 bottom
C5022  220p/25V_2  [C0201]  53.58 30.79 0 bottom
C5023  *EGA10402V05AH_0.2p  [R0402]  180.3 60.51 270 top
C5024  *EGA10402V05AH_0.2p  [R0402]  43.52 53.6 90 top
C5025  *EGA10402V05AH_0.2p  [R0402]  43.24 51.11 90 top
C5100  *10P/50V_4  [C0402]  174 67.44 270 top
C5101  0.1U/16V_4  [C0402]  165.49 74.05 180 top
C5102  0.1U/16V_4  [C0402]  165.18 67.47 180 top
C5103  0.1U/16V_4  [C0402]  174.81 72.88 180 top
C5104  *0.1U/16V_4  [C0402]  165.62 66.12 90 top
C5205  0.1U/16V_4  [C0402]  205.09 14.92 180 top
C5206  4.7U/6.3V_4  [C0402]  203.23 13.11 0 top
C5207  PESD5V0X2UM  [DFN1006H4-3-1X0_6-3P]  176.67 17.73 90 bottom
C5208  PESD5V0X2UM  [DFN1006H4-3-1X0_6-3P]  185.48 13.29 135 bottom
C5300  0.1U/16V_4  [C0402]  66.91 30.28 270 top
C5301  0.1U/16V_4  [C0402]  65.95 30.43 270 top
C5302  *33P/50V_4  [C0402]  71.51 23.14 90 top
C5303  *33P/50V_4  [C0402]  67.01 24.21 0 top
C5304  *22P/50V_4  [C0402]  67.01 25.28 180 top
C5305  *0.1u/16V_2  [C0201]  73.44 132.22 0 top
C5400  4.7U/6.3V_4  [C0402]  44.15 69.68 270 top
C5401  0.1U/16V_4  [C0402]  45.37 69.5 90 top
C5402  *220P/50V_4  [C0402]  46.72 69.88 0 top
C5403  *220P/50V_4  [C0402]  46.06 65.59 0 top
C5404  0.01U/50V_4  [C0402]  168.26 99.42 180 top
C5405  0.1U/16V/X7R_4  [C0402]  42.78 110.57 180 bottom
C5406  2200P/50V_4  [C0402]  170.11 99.24 0 top
C5600  0.1U/16V_4  [C0402]  178.05 79.7 270 top
C5601  82P/50V_4  [C0402]  173.44 65.49 0 top
C5700  0.1U/16V_4  [C0402]  224.57 33.03 180 bottom
C5701  470P/50V_4  [C0402]  221.06 48.21 270 bottom
C5702  1000P/50V_4  [C0402]  224.93 29.98 270 bottom
C5703  0.1U/16V_4  [C0402]  222.75 30.7 180 top
C5704  0.1U/16V_4  [C0402]  222.75 29.68 180 top
C5705  PESD5V0X2UM  [DFN1006H4-3-1X0_6-3P]  224.11 34.65 180 top
C5706  100U/6.3V_3528  [C3528]  221.7 44.58 0 bottom
C5707  1U/6.3V_4  [C0402]  219.74 41.99 270 bottom
C5708  0.1U/16V_4  [C0402]  220.07 48.21 270 bottom
C5709  470P/50V_4  [C0402]  224.52 48.21 270 bottom
C5710  1000P/50V_4  [C0402]  223.53 48.21 90 bottom
C5711  0.1U/16V_4  [C0402]  221.39 51.24 180 bottom
C5712  0.1U/16V_4  [C0402]  221.39 50.25 180 bottom
C5713  PESD5V0X2UM  [DFN1006H4-3-1X0_6-3P]  224.28 54.21 180 bottom
C5800  0.1U/16V_4  [C0402]  201.91 112.58 180 top
C5801  0.1U/16V_4  [C0402]  201.91 113.59 180 top
C5802  0.1U/16V_4  [C0402]  201.91 111.56 180 top
C5803  0.1U/16V_4  [C0402]  201.91 110.6 180 top
C5804  0.1U/16V_4  [C0402]  201.91 109.63 180 top
C5805  0.1U/16V_4  [C0402]  201.91 108.67 180 top
C5806  0.1U/16V_4  [C0402]  201.91 107.7 180 top
C5807  0.1U/16V_4  [C0402]  201.91 106.74 180 top
C5808  0.1U/16V_4  [C0402]  205.98 103.38 270 top
C5809  0.1U/16V_4  [C0402]  206.99 103.38 270 top
C5810  0.1U/16V_4  [C0402]  204.71 108.9 0 bottom
C5811  0.01U/50V/X7R_4  [C0402]  205.6 112.58 90 bottom
C5812  0.1U/16V_4  [C0402]  204 102.37 0 top
C5813  0.1U/16V_4  [C0402]  206 114.69 90 top
C5814  0.1U/16V_4  [C0402]  207.02 114.69 90 top
C5815  0.1U/25V_4  [C0402]  210.7 108.49 0 top
C5816  0.1U/25V_4  [C0402]  210.7 109.46 0 top
C5817  0.1U/16V_4  [C0402]  204.12 114.08 180 top
C5818  0.1U/16V_4  [C0402]  204.12 115.07 180 top
C5819  0.1U/25V_4  [C0402]  210.68 111.4 0 top
C5820  0.1U/25V_4  [C0402]  210.68 110.43 0 top
C5821  1U/6.3V_4  [C0402]  198.1 101.25 0 top
C5822  0.1U/16V_4  [C0402]  207.88 112.58 270 bottom
C5823  0.01U/50V/X7R_4  [C0402]  204.71 107.63 180 bottom
C5824  0.1U/16V_4  [C0402]  206.74 107.12 90 bottom
C5825  0.1U/16V_4  [C0402]  206.74 112.58 270 bottom
C5826  0.01U/50V/X7R_4  [C0402]  207.75 107.12 270 bottom
C5827  0.33UF/25V_4  [C0402]  210.71 106.5 180 top
C5828  0.33UF/25V_4  [C0402]  210.71 107.51 180 top
C5829  0.33UF/25V_4  [C0402]  210.33 113.39 180 top
C5830  0.33UF/25V_4  [C0402]  210.33 112.37 180 top
C6100  0.1U/16V_4  [C0402]  192.62 114.58 90 top
C6101  0.1U/16V_4  [C0402]  193.61 114.58 90 top
C6102  1uF/6.3V_4  [C0402]  194.6 114.58 270 top
C6103  1uF/6.3V_4  [C0402]  190.89 114.3 180 top
C6104  390P/50V_4  [C0402]  184.13 109.35 90 top
C6105  390P/50V_4  [C0402]  184.23 106.76 270 top
C6106  0.1U/16V_4  [C0402]  185.25 104.96 270 top
C6107  0.1U/16V_4  [C0402]  183.02 109.35 90 top
C6108  1uF/6.3V_4  [C0402]  181.9 109.35 270 top
C6202  10P/50V_4  [C0402]  61.32 30.26 90 bottom
C6203  10P/50V_4  [C0402]  63.1 30.26 90 bottom
C6204  0.1U/16V_4  [C0402]  66.15 30.26 270 bottom
C6205  12P/50V_4  [C0402]  64.12 30.26 90 bottom
C6206  12P/50V_4  [C0402]  65.13 30.26 90 bottom
C6300  *47U/6.3V_6  [C0603]  222.82 94.09 180 top
C6301  *47U/6.3V_6  [C0603]  222.82 92.66 180 top
C6302  *0.47U/25V_4  [C0402]  220.71 103.48 180 top
C6303  10u/25V_8  [C0805]  232.4 108.27 270 top
C6304  1000p/25V_2  [C0201]  225.53 97.26 180 top
C6305  47U/6.3V_6  [C0603]  223.45 91.24 180 top
C7500  *0.1u/6.3V_2  [C0201]  54.44 60.69 180 top
C7600  0.1U/16V_4  [C0402]  11.03 104.65 0 top
C7601  220P/50V_4  [C0402]  10.3 106.71 0 top
C7602  220P/50V_4  [C0402]  10.3 105.62 0 top
C7603  1000P/50V_4  [C0402]  10.3 107.68 180 top
C7604  0.1U/16V_4  [C0402]  45.45 28.38 0 bottom
C7605  0.1U/16V_4  [C0402]  43.63 28.37 180 bottom
C7606  0.1U/16V_4  [C0402]  9 115.63 180 top
C7607  1U/6.3V_4  [C0402]  43.29 34.6 270 top
C7608  1U/6.3V_4  [C0402]  40.24 34.6 270 top
C7609  4.7U/6.3V_4  [C0402]  45.32 34.6 90 top
C7610  0.1U/16V_4  [C0402]  38.69 32.42 0 top
C7611  0.1U/16V_4  [C0402]  40.62 27.59 90 top
C7612  0.1U/16V_4  [C0402]  38.23 33.76 270 top
C7613  0.1U/16V_4  [C0402]  39.27 34.44 270 top
C7614  4.7U/6.3V_4  [C0402]  47.71 32.62 0 top
C7615  0.1U/16V_4  [C0402]  42.27 34.6 270 top
C7616  *0.1U/16V_4  [C0402]  13.42 109.53 270 top
C7617  0.01U/50V_4  [C0402]  41.26 34.6 270 top
C7618  33P/50V_4  [C0402]  39.21 28.51 0 bottom
C7619  *10u/6.3V_4  [C0402_2]  63.15 125.48 90 bottom
C7620  0.1U/16V_4  [C0402]  46.49 24.59 90 top
C7621  *4.7p/50V_4  [C0402]  47.3 30.46 180 top
C7622  *4.7p/50V_4  [C0402]  73.57 126.47 180 top
C7623  *4.7p/50V_4  [C0402]  41.34 31.12 180 bottom
C7624  *4.7p/50V_4  [C0402]  37.32 27.26 0 top
C7625  *4.7p/50V_4  [C0402]  36.64 28.55 180 bottom
C7626  *4.7p/50V_4  [C0402]  40.93 28.72 180 bottom
C7627  220P/50V_4  [C0402]  30.27 25.14 0 top
C7628  220P/50V_4  [C0402]  30.21 24.31 270 bottom
C7629  220P/50V_4  [C0402]  45.14 24.41 180 top
C7700  *10P/50V_4  [C0402]  164.45 65.94 90 top
C7701  0.1U/16V_4  [C0402]  28.48 121.32 90 top
C7702  0.1U/16V_4  [C0402]  29.9 109.68 270 top
C7800  68P/50V_4  [C0402]  166.63 22.79 270 top
C7801  2200P/50V_4  [C0402]  176.34 30.56 90 top
C7802  68P/50V_4  [C0402]  114.59 29.44 270 top
C7803  68P/50V_4  [C0402]  175.29 30.56 90 top
C7804  2.2u/25V_4  [C0402]  113.6 29.44 270 top
C7805  2.2u/25V_4  [C0402]  153.98 22.59 270 top
C7806  2200P/50V_4  [C0402]  184.21 23.41 270 top
C7807  2.2u/25V_4  [C0402]  167.62 22.79 270 top
C7808  68P/50V_4  [C0402]  152.97 22.59 270 top
C7809  2200P/50V_4  [C0402]  146.13 23.65 270 top
C7810  2.2u/25V_4  [C0402]  177.35 30.56 90 top
C7811  68P/50V_4  [C0402]  176.13 22.79 270 top
C7812  2200P/50V_4  [C0402]  73.9 84.77 45 bottom
C7813  2.2u/25V_4  [C0402]  72.53 85.43 135 bottom
C7814  68P/50V_4  [C0402]  69.48 81.49 135 bottom
C7815  2200P/50V_4  [C0402]  68.81 77.2 180 bottom
C7816  2.2u/25V_4  [C0402]  68.81 75.05 180 bottom
C7817  68P/50V_4  [C0402]  70.24 82.25 135 bottom
C7818  2200P/50V_4  [C0402]  68.81 73.97 180 bottom
C7819  2.2u/25V_4  [C0402]  74.66 84 45 bottom
C7820  68P/50V_4  [C0402]  68.81 78.28 180 bottom
C7821  2200P/50V_4  [C0402]  75.4 83.29 45 bottom
C7822  2.2u/25V_4  [C0402]  68.81 76.12 180 bottom
C7823  68P/50V_4  [C0402]  68.79 80.8 135 bottom
C7824  68P/50V_4  [C0402]  147.13 20.3 90 top
C7825  2200P/50V_4  [C0402]  146.13 20.33 90 top
C7826  0.1U/16V_4  [C0402]  154.85 14.38 270 top
C7827  2200P/50V_4  [C0402]  201.81 18.14 0 top
C7828  2.2u/25V_4  [C0402]  201.33 17.15 0 top
C7829  68P/50V_4  [C0402]  202.42 19.13 0 top
C7830  2200P/50V_4  [C0402]  223.86 88.37 180 top
C7831  2.2u/25V_4  [C0402]  224.9 87.4 180 top
C7832  68P/50V_4  [C0402]  223.48 89.4 180 top
C7833  2200P/50V_4  [C0402]  193.17 33.83 180 top
C7834  2.2u/25V_4  [C0402]  193.17 34.8 180 top
C7835  68P/50V_4  [C0402]  193.16 32.84 180 top
C7836  2.2u/25V_4  [C0402]  217.53 47.6 180 top
C7837  68P/50V_4  [C0402]  217.47 46.62 180 top
C7838  2200P/50V_4  [C0402]  214.16 79.76 180 top
C7839  2.2u/25V_4  [C0402]  214.16 80.75 180 top
C7840  68P/50V_4  [C0402]  214.16 78.77 180 top
C7841  0.1U/16V_4  [C0402]  52.76 106.61 180 top
C7842  0.1U/25V_4  [C0402]  52.64 91.85 0 top
C7843  68P/50V_4  [C0402]  57.01 98.46 180 top
C7844  68P/50V_4  [C0402]  65.07 117.97 0 top
C7845  68P/50V_4  [C0402]  103.87 119.84 270 top
C7846  2200P/50V_4  [C0402]  98.53 107.63 270 top
C7847  2.2u/25V_4  [C0402]  97.52 107.88 270 top
C7848  68P/50V_4  [C0402]  99.55 107.63 270 top
C7849  68P/50V_4  [C0402]  115.4 112.93 90 top
C7850  2.2u/25V_4  [C0402]  47.15 129.16 0 top
C7851  2.2u/25V_4  [C0402]  211.87 79.33 270 bottom
C7852  2.2u/25V_4  [C0402]  71.46 39.88 0 top
C7853  2.2u/25V_4  [C0402]  148.8 41.2 0 top
C7854  68P/50V_4  [C0402]  148.8 40.24 0 top
C7855  2.2u/25V_4  [C0402]  76.84 84.11 135 bottom
C7856  2.2u/25V_4  [C0402]  81.87 85.71 0 bottom
C7857  2.2u/25V_4  [C0402]  144.53 128.95 180 bottom
C7858  2.2u/25V_4  [C0402]  82.67 103.59 270 bottom
C7859  2.2u/25V_4  [C0402]  148.79 120.6 180 bottom
C7860  2.2u/25V_4  [C0402]  41.77 127.95 180 top
C7861  2.2u/25V_4  [C0402]  43.54 127.95 180 top
C7862  68P/50V_4  [C0402]  184.42 24.01 0 bottom
C7863  2.2u/25V_4  [C0402]  122.55 125.08 0 bottom
C7864  68P/50V_4  [C0402]  122.55 126.07 0 bottom
C7865  2.2u/25V_4  [C0402]  116.7 112.93 90 top
C7866  2.2u/25V_4  [C0402]  76.44 87.56 270 top
C7867  2.2u/25V_4  [C0402]  20.3 117.79 180 bottom
C7868  68P/50V_4  [C0402]  161.78 21.39 0 bottom
C7869  0.1U/16V_4  [C0402]  155.3 41.84 180 top
C7870  68P/50V_4  [C0402]  179.94 40.06 270 top
C7871  0.1U/16V_4  [C0402]  41.77 128.96 180 top
C7872  0.1U/16V_4  [C0402]  29.57 128.2 0 top
C7873  68P/50V_4  [C0402]  29.19 124.14 270 top
C7874  68P/50V_4  [C0402]  29.32 126.17 90 top
CN3400  GS12401-1011-9H  [51693-0400T-V01-40P-L]  33.4 126.89 180 bottom
CN3500  DP/HDMI CONN  [HDMI-HMRF2-AK520C-20P-SMT]  233.6 71.62 270 bottom
CN3600  INT SPEAKER CONN  [50281-0040N-001-4P-L]  161.4 125.39 90 bottom
CN3601  DFTJ06FRA94  [AUDIO-2SJ3095-186211F-6P]  237.37 15.72 270 bottom
CN4000  RJ45_CONN  [RJ45-2RJ3Y35-108211F-12P]  235.05 93.71 90 top
CN4100  LOTES_APCI0019-P00*A  [NGFF-NFSE0-S6710-TPH4-KE-SMT]  169.95 88.21 0 bottom
CN4200  WWAN_NGFF CONN  [NGFF-NFSB0-S6710-TPH4-KB-SMT]  197.7 77.64 0 bottom
CN4201  SIM_CONN  [SIMCRAD-CPMPAT7-08GLBS1-8P]  208 47.96 180 bottom
CN4300  SSD_NGFF_CONN_75P  [NGFF-NFSM0-S6710-TPH4-75P-KM]  208.55 14.59 90 bottom
CN4400  SATA HDD  [FPC-51625-0100T-V01-10P-L]  221.05 19.43 180 bottom
CN5000  KB CONN  [51540-04201-V02-42P-L]  40.28 45.97 90 bottom
CN5001  Leap Motion  [51614-00801-V02-8P-L]  139.2 11.49 180 bottom
CN5201  FPR conn.  [FH34S-8S-0_5SH-8P-L]  180.2 11.54 180 bottom
CN5400  FAN Connect  [50281-0040N-001-4P-L]  42.23 67.29 90 bottom
CN5700  USB3.0 CONN  [UB3-54956-00902-V02-9P]  237.24 32.48 270 bottom
CN5701  USB3.0 CONN  [UB3-54956-00902-V02-9P]  237.24 51.54 270 bottom
CN6200  Click Pad CONN  [51619-01001-V05-10P-L]  61.76 24.84 180 bottom
CN6300  TYPE-C  [UB31-AUSB0152-P604A-24P]  234.04 115.34 270 bottom
CN7600  HDT CONN  [FPC-CF5020FD0RT-05-NH-20P-L]  3.85 109.59 270 top
CN7601  SMD FPC 22P  [FPC-51519-02201-V01-22P-L]  39.49 20.99 180 bottom
CN7602  *SENSOR CONN  [51625-01201-001-12P-L]  72.16 131.94 90 bottom
CN7603  *2ND CAMERA  [FPC-51625-0100T-V01-10P-L]  37.45 22.66 0 top
CN7700  *Samtec BSH-030-01  [BSH-030-01-L-D-A-TR-60P-RUV]  33.51 115.75 0 top
CN7701  debug_CONN_30P  [50150-03001-001-30P-LDH]  162.03 74.73 180 bottom
CN7702  FPR conn.  [51614-00801-V02-8P-L]  172.2 9.41 180 bottom
D400  BAT54CW-7-F  [SOT323_213-2_1-1_3-2N7002W]  61.43 62.82 90 top
D3300  *RB500V-40  [D-SOD323-1_85X1_25-0_95H]  147.86 8.95 180 bottom
D3600  Clamp-Diode  [C0402]  227.72 8.44 90 top
D3601  Clamp-Diode  [C0402]  224.85 17.29 180 top
D3603  Clamp-Diode  [C0402]  226.75 8.44 90 top
D3604  *MEK500V-40  [D-SOD323-1_85X1_25-0_95H]  214.99 18.78 0 top
D3605  Clamp-Diode  [C0402]  226.86 23.7 270 top
D4200  MEK500V-40  [D-SOD323-1_85X1_25-0_95H]  193.99 83.73 0 top
D4201  RB500V-40  [D-SOD323-1_85X1_25-0_95H]  197.04 74.81 270 top
D4300  RB500V-40  [D-SOD323-1_85X1_25-0_95H]  205.9 8.57 90 top
D4700  *RB500V-40  [D-SOD323-1_85X1_25-0_95H]  217.1 59.95 270 top
D5000  BAW56DW  [SOT363-2_1-65-6P]  46.06 47.86 270 top
D5001  BAW56DW  [SOT363-2_1-65-6P]  43.06 45.24 0 top
D5002  BAW56DW  [SOT363-2_1-65-6P]  40.8 47.63 180 top
D5003  BAW56DW  [SOT363-2_1-65-6P]  40.78 38.46 0 top
D6200  RB500V-40  [D-SOD323-1_85X1_25-0_95H]  57.87 30 270 bottom
D6300  P4SMAFJ20A  [D-3_8X2_5]  222.87 106.23 90 top
D6301  AZ4024-01F.R7GR  [D-1X0_6-0_6H]  230.43 113.58 180 top
D6302  AZ4024-01F.R7GR  [D-1X0_6-0_6H]  230.43 114.8 180 top
D6303  AZ4024-01F.R7GR  [D-1X0_6-0_6H]  233.56 116.77 90 top
D6304  AZ4024-01F.R7GR  [D-1X0_6-0_6H]  229.58 116.16 180 top
D7600  MEK500V-40  [D-SOD323-1_85X1_25-0_95H]  41.31 36.28 0 top
D7601  RB501V-40  [D-SOD323-1_85X1_25-0_95H]  47.2 29.65 90 bottom
D7602  RB501V-40  [D-SOD323-1_85X1_25-0_95H]  45.45 31.17 90 bottom
EC2800  120P/50V_4  [C0402]  78.85 41.1 270 top
EC2801  2200P/50V_4  [C0402]  80.58 41 180 top
EC2802  120P/50V_4  [C0402]  82.08 43.11 90 top
EC2803  68P/50V_4  [C0402]  86.6 41.59 180 top
EC2804  2.2U/6.3V_4  [C0402]  53.47 40.65 180 top
EC2805  68P/50V_4  [C0402]  88.48 41.31 0 top
EC2806  2.2U/6.3V_4  [C0402]  177.56 40.85 90 top
EC2807  0.1U/16V_4  [C0402]  97.04 39.78 0 top
EC2808  0.1U/16V_4  [C0402]  90.28 40.19 180 top
EC2809  120P/50V_4  [C0402]  65.82 40.7 0 top
EC2810  0.1U/16V_4  [C0402]  75.12 41 0 top
EC2811  68P/50V_4  [C0402]  68.72 40.7 180 top
EC2812  82P 50V_4  [C0402]  106.08 39.96 90 top
EC2813  0.1U/16V_4  [C0402]  102.37 41.46 90 top
EC2814  2.2U/6.3V_4  [C0402]  82.96 40.52 90 top
EC2815  2.2U/6.3V_4  [C0402]  93.25 43.64 180 top
EC2816  2200P/50V_4  [C0402]  116.42 37.32 90 top
EC2817  2.2U/10V_4  [C0402]  115.4 37.32 90 top
EC2818  2.2U/10V_4  [C0402]  117.79 39.2 270 top
EC2819  82P/50V_4  [C0402]  114.41 37.32 90 top
EC2820  82P/50V_4  [C0402]  188.5 37.93 270 top
EC2821  2.2U/10V_4  [C0402]  160.46 40.09 180 top
EC2822  2200P/50V_4  [C0402]  184.51 37.93 270 top
EC2823  82P/50V_4  [C0402]  153.07 44.23 0 top
EC3400  *100p/50V_4  [C0402]  24.7 130.05 270 top
EC3600  0.1U/16V_4  [C0402]  225.79 8.11 90 top
EC3601  0.1U/16V_4  [C0402]  225.89 23.7 270 top
EC3602  0.1U/16V_4  [C0402]  228.84 22.87 270 top
EC3603  0.1U/16V_4  [C0402]  224.49 6.62 180 top
EC3605  0.1U/16V_4  [C0402]  223.73 20.45 0 top
EC3606  0.1U/16V_4  [C0402]  223.73 18.52 0 top
EC3607  0.1U/16V_4  [C0402]  223.73 19.49 0 top
EC3608  0.1U/16V_4  [C0402]  223.68 21.42 0 top
EC3609  *33P/50V_4  [C0402]  213.42 9.2 180 top
EC3610  0.1U/16V_4  [C0402]  224.9 23.73 270 top
EC3611  *10P/50V_4  [C0402]  214.03 13.06 180 top
EC3612  *10P/50V_4  [C0402]  214.92 8.03 90 top
EC3613  0.1U/16V_4  [C0402]  227.85 23.73 270 top
EC4300  10U/6.3V_4  [C0402]  202.78 14.55 0 top
EC9700  *1N/50V_4  [C0402]  225.15 109.15 90 top
EC9701  22u/25V_8  [C0805]  141.23 30.46 270 top
EC9702  *22u/25V_8  [C0805]  149.82 28.83 180 top
EC9703  22u/25V_8  [C0805]  138.57 30.46 270 top
EC9704  *22u/25V_8  [C0805]  136.56 31.02 270 top
F3400  FUSE1A6V_POLY  [F2_1X1_35-2_2-0_75H]  27.67 125.66 270 top
F3401  FUSE SMD 1.5A 24V POLY  [F4_55X3_24-5_23-1_8H]  50.63 127.28 0 bottom
F3402  FUSE SMD 1.1A 6V POLY  [F2_1X1_35-2_2-0_75H]  38.74 124.41 180 top
F5200  FUSE SMD 0.1A 15V POLY  [F2_1X1_35-2_2-0_75H]  171.84 18.5 180 bottom
F7600  *FUSE0.35A 6V_POLY  [R0603]  76.11 126.83 90 top
H7900  *H-C138D83PT  [H-C138D83PT]  77.05 135.95 0 top
H7901  *H-O177X138D122X83PT  [H-O177X138D122X83PT]  238.51 2.29 180 top
H7902  *H-C315I252D252P2  [H-C315I252D252P2]  82.9 130.79 0 top
H7903  -  [H-TC197IC122D122PT]  130.3 14.59 180 bottom
H7904  -  [H-TC197IC122D122PT]  169.95 116.46 180 bottom
H7905  -  [H-TC197IC122D122PT]  197.7 117.89 180 bottom
H7906  *H-C276D98P2  [H-C276D98P2]  9.1 99.59 0 top
H7908  *H-415WD-2  [H-415WD-2]  237.2 106.31 0 top
H7909  *H-TC236BC91D91PT  [H-TC236BC91D91PT]  220.05 85.13 0 top
H7910  *H-415WD-1  [H-415WD-1]  32.67 30.09 0 top
H7911  *o-x8j-2-1p2  [O-X8J-2-1P2]  51.9 21.84 0 top
H7912  *o-x8j-1-1p2  [O-X8J-1-1P2]  113.9 21.84 0 top
H7913  *SPAD-415WD-1NP  [SPAD-415WD-1NP]  126.13 6.29 0 top
H7914  *H-TC315BC276D91P2  [H-TC315BC276D91P2]  238.5 6.29 0 top
H7916  *H-TC150IC150BC197D150PB  [H-TC150IC150BC197D150PB]  86.45 105.19 180 bottom
H7917  *H-TC150IC150BC197D150PB  [H-TC150IC150BC197D150PB]  146.45 105.19 180 bottom
H7918  *H-TC150IC150BC197D150PB  [H-TC150IC150BC197D150PB]  146.45 76.59 180 bottom
H7919  *H-TC150IC150BC197D150PB  [H-TC150IC150BC197D150PB]  86.45 76.59 180 bottom
H7920  *H-C276I91D91P2  [H-C276I91D91P2]  120.95 66.79 0 top
H7921  *H-TC315IC91BC276D91P2  [H-TC315IC91BC276D91P2]  230.3 122.11 0 top
H7922  *H-O122X83D122X83N  [H-O122X83D122X83N]  236 123.84 0 top
H7923  *H-O374X276D189X91P2  [H-O374X276D189X91P2]  210.6 30.09 0 top
H7924  *H-C276D91P2  [H-C276D91P2]  23.05 19.66 0 top
H7925  *SPAD-415WD-2NP  [SPAD-415WD-2NP]  126.13 6.29 180 bottom
H7926  *H-O63X83D63X83N  [H-O63X83D63X83N]  233.75 105.78 0 top
H7927  *H-O63X83D63X83N  [H-O63X83D63X83N]  223.05 85.13 0 top
H7928  *h-c217d98p2  [H-C217D98P2]  11.6 95.79 0 top
H7931  *2D-BARCODE-8X8-S  [2D-BARCODE-8X8-S]  36.18 83.75 270 bottom
H7932  *2D-BARCODE-8X8-S  [2D-BARCODE-8X8-S]  71.89 54.03 180 bottom
H7933  *2D-BARCODE-8X8-S  [2D-BARCODE-8X8-S]  60.82 86.49 270 top
JDIM2800  DDR4-DIMM0_H=4_RVS  [DDR4-D4AR0-26010-1P40-RVS-SMT]  82.48 41.13 180 bottom
JDIM2801  DDR3-DIMM0_H=5.2_RVS  [DDR4-D4AR0-26010-1P40-RVS-SMT]  159.44 41.13 180 bottom
L400  0_4  [R0402]  154.52 97.8 0 bottom
L401  *MCM2012B900GBE  [CHOKE-DLP0NSN900HL2L]  142.23 102.36 270 bottom
L402  120/300MA  [R0402]  128.18 107.42 180 top
L3400  HCB1608KF-181T15_S0_6  [R0603]  31.03 124.26 0 top
L3401  120/300MA_S0_4  [R0402]  38.62 128.38 270 top
L3402  120/300MA_S0_4  [R0402]  39.63 128.38 270 top
L3600  *0_6/S  [S0603]  162.16 127.44 0 top
L3601  *0_6/S  [S0603]  162.16 125.99 0 top
L3602  *0_6/S  [S0603]  163.66 122.61 90 top
L3603  *0_6/S  [S0603]  164.91 118.14 90 top
L3604  *0_6/S  [S0603]  221.83 19.39 90 top
L3605  *Short_1206  [S1206]  220.4 24.83 180 top
L4000  4.7uH_3.2x2.5x2  [L3_2X2_5-3_2]  198.14 64.67 0 bottom
L4200  *DLP11SN900HL2L  [CHOKE-DLP11SN900HL2L-4P-1]  189.47 75.9 0 top
L4700  HCB1608KF-181T15  [R0603]  193.1 45.7 0 top
L5200  *MCM2012B900GBE  [FILTER-MCM2012B900GBE-4P]  187.46 11.31 315 bottom
L5700  MCM2012B900GBE  [FILTER-MCM2012B900GBE-4P]  221.29 32.82 180 top
L5701  MCM2012B900GBE  [FILTER-MCM2012B900GBE-4P]  221.67 54.18 180 bottom
L7600  MCM2012B900GBE  [FILTER-MCM2012B900GBE-4P]  10.37 109.43 0 top
NOREF  -  []  12.3 114.99 0 top
NOREF#2  -  [unnamed#2]  228.1 6.43 0 top
NOREF#3  -  [unnamed#2]  26.78 25.08 0 top
NOREF#4  -  []  199.5 -36.01 0 top
NOREF#5  -  [unnamed#2]  155.68 128.45 0 top
NOREF#6  -  []  21.58 -47.07 0 top
NOREF#7  -  [unnamed#2]  26.78 25.08 180 bottom
NOREF#8  -  [unnamed#2]  155.68 128.45 180 bottom
NOREF#9  -  [unnamed#2]  225.92 11.74 180 bottom
NOREF#10  -  []  18.91 113.98 180 bottom
PC8000  0.1u/25V_4  [C0402]  215.25 106.93 270 bottom
PC8001  0.1u/25V_4  [C0402]  203.36 97.82 90 top
PC8002  1u/25V_4  [C0402]  204.94 99.4 0 top
PC8003  0.1u/25V_4  [C0402]  208.09 94.39 0 top
PC8004  1u/25V_4  [C0402]  207.15 92.89 270 top
PC8100  1N/50V_4  [C0402]  3.36 113.54 270 bottom
